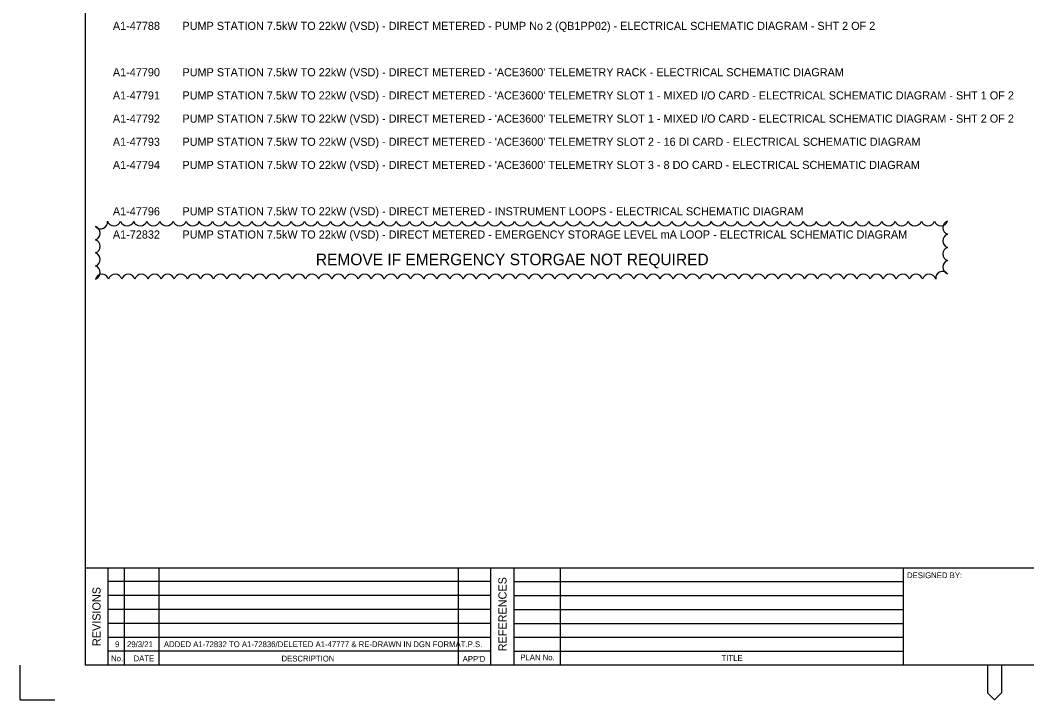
# Model space of a CAD drawing. Extents: x 0 to 841, y 0 to 594.
# Drawn here: x 0 to 434.2, y 0 to 293.2 of the extents above; entities that cross this region are included whole.
import ezdxf

# ---------------------------------------------------------------- set-up
doc = ezdxf.new("R2010")
doc.units = 0
doc.layers.add('A1BORDER', color=7, linetype='Continuous')
doc.layers.add('Level 1', color=7, linetype='Continuous')

msp = doc.modelspace()

# ---------------------------------------------------------------- linework, layer by layer
at = {"layer": 'A1BORDER'}
for p, q in [((28, 581), (28, 15)), ((28, 57), (829, 57)), ((38, 15), (38, 57)), ((45, 15), (45, 57)), ((60, 15), (60, 57)), ((189, 15), (189, 57)), ((203, 15), (203, 57)), ((213, 15), (213, 57)), ((233, 15), (233, 57)), ((381, 15), (381, 57)), ((203, 51), (38, 51)), ((213, 51), (381, 51)), ((203, 45), (38, 45)), ((213, 45), (381, 45)), ((203, 39), (38, 39)), ((213, 39), (381, 39)), ((203, 33), (38, 33)), ((213, 33), (381, 33)), ((38, 27), (203, 27)), ((213, 27), (381, 27)), ((203, 21), (38, 21)), ((213, 21), (381, 21)), ((0, 0), (0, 15)), ((829, 15), (28, 15)), ((417.19, 15), (417.19, 3)), ((423.19, 15), (423.19, 3)), ((0, 0), (15, 0)), ((417.19, 3), (420.19, 0)), ((423.19, 3), (420.19, 0))]:
    msp.add_line(p, q, dxfattribs=at)
at = {"layer": 'Level 1'}
for centre, start, end in [((34.7, 206.14), 222.0611, 7.0611), ((31.61, 201.32), 287.5, 72.5), ((40.48, 207.39), 197.5, 342.5), ((46.14, 207.39), 197.5, 342.5), ((51.8, 207.39), 197.5, 342.5), ((57.46, 207.39), 197.5, 342.5), ((63.13, 207.39), 197.5, 342.5), ((68.79, 207.39), 197.5, 342.5), ((74.45, 207.39), 197.5, 342.5), ((80.11, 207.39), 197.5, 342.5), ((85.77, 207.39), 197.5, 342.5), ((91.44, 207.39), 197.5, 342.5), ((97.1, 207.39), 197.5, 342.5), ((102.76, 207.39), 197.5, 342.5), ((108.42, 207.39), 197.5, 342.5), ((114.08, 207.39), 197.5, 342.5), ((119.74, 207.39), 197.5, 342.5), ((125.41, 207.39), 197.5, 342.5), ((131.07, 207.39), 197.5, 342.5), ((136.73, 207.39), 197.5, 342.5), ((142.39, 207.39), 197.5, 342.5), ((148.05, 207.39), 197.5, 342.5), ((153.71, 207.39), 197.5, 342.5), ((159.38, 207.39), 197.5, 342.5), ((165.04, 207.39), 197.5, 342.5), ((170.7, 207.39), 197.5, 342.5), ((176.36, 207.39), 197.5, 342.5), ((182.02, 207.39), 197.5, 342.5), ((187.68, 207.39), 197.5, 342.5), ((193.35, 207.39), 197.5, 342.5), ((199.01, 207.39), 197.5, 342.5), ((204.67, 207.39), 197.5, 342.5), ((210.33, 207.39), 197.5, 342.5), ((215.99, 207.39), 197.5, 342.5), ((221.66, 207.39), 197.5, 342.5), ((227.32, 207.39), 197.5, 342.5), ((232.98, 207.39), 197.5, 342.5), ((238.64, 207.39), 197.5, 342.5), ((244.3, 207.39), 197.5, 342.5), ((249.96, 207.39), 197.5, 342.5), ((255.63, 207.39), 197.5, 342.5), ((261.29, 207.39), 197.5, 342.5), ((266.95, 207.39), 197.5, 342.5), ((272.61, 207.39), 197.5, 342.5), ((278.27, 207.39), 197.5, 342.5), ((283.93, 207.39), 197.5, 342.5), ((289.6, 207.39), 197.5, 342.5), ((295.26, 207.39), 197.5, 342.5), ((300.92, 207.39), 197.5, 342.5), ((306.58, 207.39), 197.5, 342.5), ((312.24, 207.39), 197.5, 342.5), ((317.9, 207.39), 197.5, 342.5), ((323.57, 207.39), 197.5, 342.5), ((329.23, 207.39), 197.5, 342.5), ((334.89, 207.39), 197.5, 342.5), ((340.55, 207.39), 197.5, 342.5), ((346.21, 207.39), 197.5, 342.5), ((351.88, 207.39), 197.5, 342.5), ((357.54, 207.39), 197.5, 342.5), ((363.2, 207.39), 197.5, 342.5), ((368.86, 207.39), 197.5, 342.5), ((374.52, 207.39), 197.5, 342.5), ((380.18, 207.39), 197.5, 342.5), ((385.85, 207.39), 197.5, 342.5), ((391.51, 207.39), 197.5, 342.5), ((397.17, 207.39), 197.5, 342.5), ((400.89, 203.67), 107.5, 252.5), ((400.89, 198.01), 107.5, 252.5), ((31.61, 195.65), 287.5, 72.5), ((31.61, 189.99), 287.5, 72.5), ((400.89, 192.35), 107.5, 252.5), ((31.61, 184.33), 287.5, 72.5), ((400.89, 186.68), 107.5, 252.5), ((35.33, 180.61), 17.5, 162.5), ((40.99, 180.61), 17.5, 162.5), ((46.65, 180.61), 17.5, 162.5), ((52.32, 180.61), 17.5, 162.5), ((57.98, 180.61), 17.5, 162.5), ((63.64, 180.61), 17.5, 162.5), ((69.3, 180.61), 17.5, 162.5), ((74.96, 180.61), 17.5, 162.5), ((80.62, 180.61), 17.5, 162.5), ((86.29, 180.61), 17.5, 162.5), ((91.95, 180.61), 17.5, 162.5), ((97.61, 180.61), 17.5, 162.5), ((103.27, 180.61), 17.5, 162.5), ((108.93, 180.61), 17.5, 162.5), ((114.6, 180.61), 17.5, 162.5), ((120.26, 180.61), 17.5, 162.5), ((125.92, 180.61), 17.5, 162.5), ((131.58, 180.61), 17.5, 162.5), ((137.24, 180.61), 17.5, 162.5), ((142.9, 180.61), 17.5, 162.5), ((148.57, 180.61), 17.5, 162.5), ((154.23, 180.61), 17.5, 162.5), ((159.89, 180.61), 17.5, 162.5), ((165.55, 180.61), 17.5, 162.5), ((171.21, 180.61), 17.5, 162.5), ((176.87, 180.61), 17.5, 162.5), ((182.54, 180.61), 17.5, 162.5), ((188.2, 180.61), 17.5, 162.5), ((193.86, 180.61), 17.5, 162.5), ((199.52, 180.61), 17.5, 162.5), ((205.18, 180.61), 17.5, 162.5), ((210.84, 180.61), 17.5, 162.5), ((216.51, 180.61), 17.5, 162.5), ((222.17, 180.61), 17.5, 162.5), ((227.83, 180.61), 17.5, 162.5), ((233.49, 180.61), 17.5, 162.5), ((239.15, 180.61), 17.5, 162.5), ((244.82, 180.61), 17.5, 162.5), ((250.48, 180.61), 17.5, 162.5), ((256.14, 180.61), 17.5, 162.5), ((261.8, 180.61), 17.5, 162.5), ((267.46, 180.61), 17.5, 162.5), ((273.12, 180.61), 17.5, 162.5), ((278.79, 180.61), 17.5, 162.5), ((284.45, 180.61), 17.5, 162.5), ((290.11, 180.61), 17.5, 162.5), ((295.77, 180.61), 17.5, 162.5), ((301.43, 180.61), 17.5, 162.5), ((307.09, 180.61), 17.5, 162.5), ((312.76, 180.61), 17.5, 162.5), ((318.42, 180.61), 17.5, 162.5), ((324.08, 180.61), 17.5, 162.5), ((329.74, 180.61), 17.5, 162.5), ((335.4, 180.61), 17.5, 162.5), ((341.06, 180.61), 17.5, 162.5), ((346.73, 180.61), 17.5, 162.5), ((352.39, 180.61), 17.5, 162.5), ((358.05, 180.61), 17.5, 162.5), ((363.71, 180.61), 17.5, 162.5), ((369.37, 180.61), 17.5, 162.5), ((375.04, 180.61), 17.5, 162.5), ((380.7, 180.61), 17.5, 162.5), ((386.36, 180.61), 17.5, 162.5), ((392.02, 180.61), 17.5, 162.5), ((397.8, 181.86), 42.0611, 187.0611)]:
    msp.add_arc(centre, 2.97, start, end, dxfattribs=at)

# ---------------------------------------------------------------- texts
at = {"layer": 'A1BORDER'}
for s, p in [('REFERENCES', (209.76, 20.96)), ('REVISIONS', (34.68, 23.2))]:
    msp.add_text(s, height=3.5, rotation=90, dxfattribs=at).set_placement(p)
for s, p in [('DESIGNED BY:', (382.5, 52.5)), ('No.', (39.21, 16.65)), ('DATE', (48.92, 16.65)), ('DESCRIPTION', (112.71, 16.57)), ("APP'D", (190.85, 16.44)), ('PLAN No.', (215.69, 17.06)), ('TITLE', (302.5, 16.81))]:
    msp.add_text(s, height=2.5, dxfattribs=at).set_placement(p)
at = {"layer": 'Level 1'}
for s, height, p in [('A1-47788', 3.5, (40, 289)), ('PUMP STATION 7.5kW TO 22kW (VSD) - DIRECT METERED - PUMP No 2 (QB1PP02) - ELECTRICAL SCHEMATIC DIAGRAM - SHT 2 OF 2', 3.49998, (70, 289)), ('A1-47790', 3.5, (40, 269)), ("PUMP STATION 7.5kW TO 22kW (VSD) - DIRECT METERED - 'ACE3600' TELEMETRY RACK - ELECTRICAL SCHEMATIC DIAGRAM", 3.49998, (70, 269)), ('A1-47791', 3.5, (40, 259)), ("PUMP STATION 7.5kW TO 22kW (VSD) - DIRECT METERED - 'ACE3600' TELEMETRY SLOT 1 - MIXED I/O CARD - ELECTRICAL SCHEMATIC DIAGRAM - SHT 1 OF 2", 3.49998, (70, 259)), ('A1-47792', 3.5, (40, 249)), ("PUMP STATION 7.5kW TO 22kW (VSD) - DIRECT METERED - 'ACE3600' TELEMETRY SLOT 1 - MIXED I/O CARD - ELECTRICAL SCHEMATIC DIAGRAM - SHT 2 OF 2", 3.49998, (70, 249)), ('A1-47793', 3.5, (40, 239)), ("PUMP STATION 7.5kW TO 22kW (VSD) - DIRECT METERED - 'ACE3600' TELEMETRY SLOT 2 - 16 DI CARD - ELECTRICAL SCHEMATIC DIAGRAM", 3.49998, (70, 239)), ('A1-47794', 3.5, (40, 229)), ("PUMP STATION 7.5kW TO 22kW (VSD) - DIRECT METERED - 'ACE3600' TELEMETRY SLOT 3 - 8 DO CARD - ELECTRICAL SCHEMATIC DIAGRAM", 3.49998, (70, 229)), ('A1-47796', 3.5, (40, 209)), ('PUMP STATION 7.5kW TO 22kW (VSD) - DIRECT METERED - INSTRUMENT LOOPS - ELECTRICAL SCHEMATIC DIAGRAM', 3.5, (70, 209)), ('A1-72832', 3.5, (40, 199)), ('PUMP STATION 7.5kW TO 22kW (VSD) - DIRECT METERED - EMERGENCY STORAGE LEVEL mA LOOP - ELECTRICAL SCHEMATIC DIAGRAM', 3.49998, (70, 199)), ('REMOVE IF EMERGENCY STORGAE NOT REQUIRED', 5, (127.54, 187.5)), ('9', 2.5, (40.94, 22.75)), ('29/3/21', 2.5, (46.09, 22.75)), ('ADDED A1-72832 TO A1-72836/DELETED A1-47777 & RE-DRAWN IN DGN FORMAT.', 2.5, (62, 22.75)), ('P.S.', 2.5, (193.02, 22.75))]:
    msp.add_text(s, height=height, dxfattribs=at).set_placement(p)

doc.saveas('drawing.dxf')
